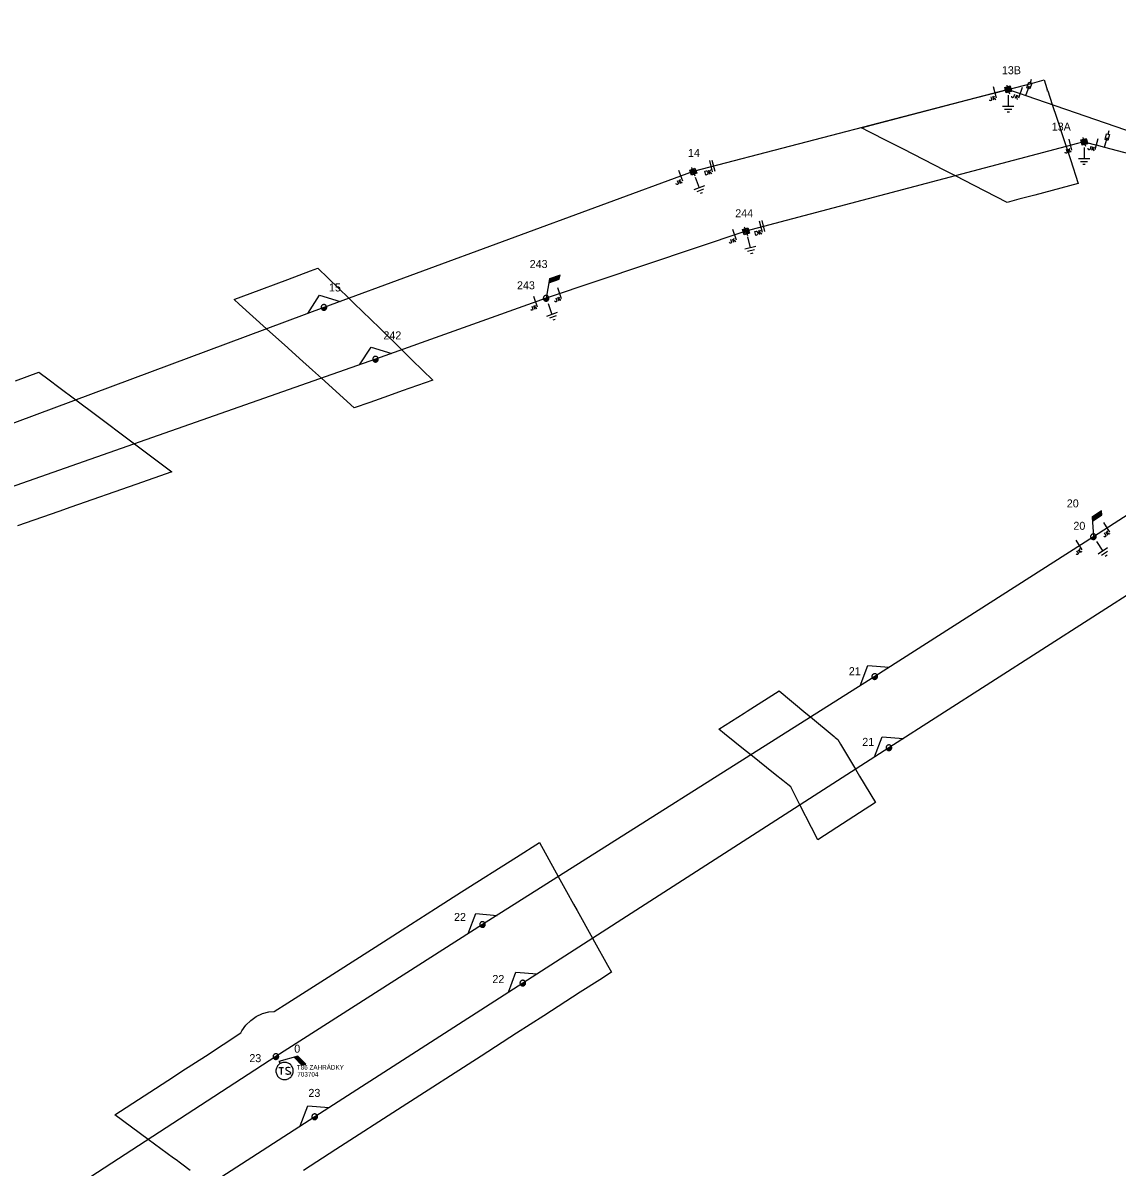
# Model space of a CAD drawing. Extents: x -540879 to -537255, y -1184046 to -1180016.
# Drawn here: x -538995.4 to -538756.2, y -1180861.8 to -1180611.6 of the extents above; entities that cross this region are included whole.
import ezdxf

# ---------------------------------------------------------------- set-up
doc = ezdxf.new("R2010")
doc.units = 0
for name, color, linetype in [('Default', 7, 'Continuous'), ('Vrstva 1', 7, 'Continuous'), ('Vrstva 11', 7, 'Continuous'), ('Vrstva 12', 7, 'Continuous'), ('Vrstva 13', 7, 'Continuous'), ('Vrstva 14', 7, 'Continuous'), ('Vrstva 15', 7, 'Continuous'), ('Vrstva 16', 7, 'Continuous'), ('Vrstva 18', 7, 'Continuous'), ('Vrstva 2', 7, 'Continuous'), ('Vrstva 25', 7, 'Continuous'), ('Vrstva 26', 7, 'Continuous'), ('Vrstva 27', 7, 'Continuous'), ('Vrstva 35', 7, 'Continuous'), ('Vrstva 4', 7, 'Continuous'), ('Vrstva 6', 7, 'Continuous')]:
    doc.layers.add(name, color=color, linetype=linetype)

# ---------------------------------------------------------------- blocks, each defined once
blk = doc.blocks.new('VN850')
at = {"layer": 'Vrstva 15'}
for points in [[(-0.56, 1.43), (-0.56, -1.07)], [(-0.01, 1.43), (-0.01, -1.07)], [(-2.09, -0.54), (-1.78, -0.54)], [(-2.09, -1.41), (-2.09, -0.54)], [(-1.78, -1.41), (-2.09, -1.41)], [(-1.78, -0.54), (-1.66, -0.6)], [(-1.67, -1.35), (-1.78, -1.41)], [(-1.59, -1.2), (-1.67, -1.35)], [(-1.66, -0.6), (-1.59, -0.75)], [(-1.59, -0.75), (-1.55, -0.96)], [(-1.55, -0.96), (-1.59, -1.2)], [(-1.26, -0.54), (-1.26, -1.41)], [(-0.85, -0.54), (-1.26, -1.09)], [(-1.13, -0.92), (-0.77, -1.41)]]:
    blk.add_lwpolyline(points, dxfattribs=at)
blk = doc.blocks.new('VN840')
at = {"layer": 'Vrstva 15'}
for points in [[(-0.01, 1.41), (-0.01, -1.09)], [(-1.51, -1.24), (-1.51, -1.15)], [(-1.48, -1.35), (-1.51, -1.24)], [(-1.33, -1.42), (-1.48, -1.35)], [(-1.27, -1.42), (-1.33, -1.42)], [(-1.13, -1.35), (-1.27, -1.42)], [(-1.09, -1.24), (-1.13, -1.35)], [(-1.09, -0.59), (-1.09, -1.24)], [(-0.68, -0.59), (-0.68, -1.42)], [(-0.68, -1.11), (-0.27, -0.59)], [(-0.54, -0.94), (-0.2, -1.42)]]:
    blk.add_lwpolyline(points, dxfattribs=at)
blk = doc.blocks.new('VN860')
at = {"layer": 'Vrstva 15'}
for points in [[(-3.74, 0), (0.01, 2.82)], [(0.01, 2.82), (3.76, 0)]]:
    blk.add_lwpolyline(points, dxfattribs=at)
blk = doc.blocks.new('VN440')
at = {"layer": 'Vrstva 2'}
for points in [[(1.22, 0), (1.21, 0.13), (1.19, 0.25), (1.16, 0.38), (1.11, 0.5), (1.05, 0.61), (0.98, 0.72), (0.9, 0.82), (0.81, 0.91), (0.71, 0.99), (0.6, 1.06), (0.49, 1.12), (0.37, 1.16), (0.25, 1.2), (0.12, 1.22), (-0.01, 1.22), (-0.14, 1.22), (-0.26, 1.2), (-0.39, 1.16), (-0.51, 1.12), (-0.62, 1.06), (-0.73, 0.99), (-0.83, 0.91), (-0.92, 0.82), (-1, 0.72), (-1.07, 0.61), (-1.13, 0.5), (-1.18, 0.38), (-1.21, 0.25), (-1.23, 0.13), (-1.24, 0), (-1.23, -0.13), (-1.21, -0.26), (-1.18, -0.38), (-1.13, -0.5), (-1.07, -0.62), (-1, -0.73), (-0.92, -0.83), (-0.83, -0.92), (-0.73, -1), (-0.62, -1.07), (-0.51, -1.13), (-0.39, -1.17), (-0.26, -1.2), (-0.14, -1.23), (-0.01, -1.23), (0.12, -1.23), (0.25, -1.2), (0.37, -1.17), (0.49, -1.13), (0.6, -1.07), (0.71, -1), (0.81, -0.92), (0.9, -0.83), (0.98, -0.73), (1.05, -0.62), (1.11, -0.5), (1.16, -0.38), (1.19, -0.26), (1.21, -0.13), (1.22, 0)], [(-1.24, 0), (1.22, 0)], [(-1.18, -0.34), (1.1, -0.34)], [(-1.01, -0.63), (0.97, -0.63)], [(-0.74, -0.92), (0.68, -0.92)]]:
    blk.add_lwpolyline(points, dxfattribs=at)
blk = doc.blocks.new('VN820')
at = {"layer": 'Vrstva 13'}
for points in [[(0, 0), (0, -2.1)], [(-0.32, -1.63), (0.34, -1.63)], [(-0.32, -2.95), (-0.32, -1.63)], [(0, -2.1), (-0.12, -1.86)], [(0, -2.1), (0.12, -1.86)], [(0.34, -1.63), (0.34, -2.95)], [(0.34, -2.95), (-0.32, -2.95)], [(0, -2.95), (0, -3.75)]]:
    blk.add_lwpolyline(points, dxfattribs=at)
blk = doc.blocks.new('VN810')
at = {"layer": 'Vrstva 14'}
for points in [[(0, -1.25), (0, -3.75)], [(1.25, -3.75), (-1.25, -3.75)], [(0.77, -4.37), (-0.8, -4.37)], [(0, -5), (-0.25, -5)], [(0.27, -5), (0, -5)]]:
    blk.add_lwpolyline(points, dxfattribs=at)
blk = doc.blocks.new('VN610')
at = {"layer": 'Vrstva 6'}
for points in [[(1.88, 0), (1.87, 0.2), (1.84, 0.39), (1.79, 0.58), (1.72, 0.77), (1.63, 0.94), (1.52, 1.11), (1.4, 1.26), (1.26, 1.4), (1.1, 1.53), (0.94, 1.63), (0.76, 1.72), (0.58, 1.8), (0.39, 1.85), (0.19, 1.88), (-0.01, 1.89), (-0.21, 1.88), (-0.4, 1.85), (-0.59, 1.8), (-0.78, 1.72), (-0.95, 1.63), (-1.12, 1.53), (-1.27, 1.4), (-1.41, 1.26), (-1.54, 1.11), (-1.64, 0.94), (-1.73, 0.77), (-1.8, 0.58), (-1.86, 0.39), (-1.89, 0.2), (-1.9, 0), (-1.89, -0.2), (-1.86, -0.39), (-1.8, -0.58), (-1.73, -0.77), (-1.64, -0.95), (-1.54, -1.11), (-1.41, -1.27), (-1.27, -1.41), (-1.12, -1.53), (-0.95, -1.64), (-0.78, -1.73), (-0.59, -1.8), (-0.4, -1.85), (-0.21, -1.88), (-0.01, -1.89), (0.19, -1.88), (0.39, -1.85), (0.58, -1.8), (0.76, -1.73), (0.94, -1.64), (1.1, -1.53), (1.26, -1.41), (1.4, -1.27), (1.52, -1.11), (1.63, -0.95), (1.72, -0.77), (1.79, -0.58), (1.84, -0.39), (1.87, -0.2), (1.88, 0)], [(-1.27, 0.78), (-0.26, 0.78)], [(-0.76, 0.78), (-0.76, -0.79)], [(1.19, 0.66), (0.94, 0.78), (0.62, 0.78), (0.37, 0.66), (0.24, 0.47), (0.24, 0.4), (0.37, 0.22), (1.12, -0.16), (1.25, -0.32), (1.25, -0.48), (1.12, -0.67), (0.87, -0.79), (0.62, -0.79), (0.49, -0.73), (0.24, -0.6)]]:
    blk.add_lwpolyline(points, dxfattribs=at)
blk = doc.blocks.new('VN001')
at = {"layer": 'Default'}
for p, q in [((1.73, 3.03), (4.14, 3.03)), ((1.76, 3.08), (4.17, 3.08)), ((1.79, 3.13), (4.2, 3.13)), ((1.82, 3.18), (4.23, 3.18)), ((1.85, 3.23), (4.26, 3.23)), ((1.87, 3.28), (4.29, 3.28)), ((1.9, 3.33), (4.32, 3.33)), ((1.93, 3.38), (4.35, 3.38)), ((1.96, 3.43), (4.37, 3.43)), ((1.99, 3.48), (4.4, 3.48)), ((2.02, 3.53), (4.43, 3.53)), ((2.05, 3.58), (4.46, 3.58)), ((2.07, 3.63), (4.49, 3.63)), ((2.1, 3.68), (4.52, 3.68)), ((2.13, 3.73), (2.54, 3.73))]:
    blk.add_line(p, q, dxfattribs=at)
blk.add_lwpolyline([(2.13, 3.73), (0, 0)], dxfattribs=at)
blk.add_lwpolyline([(4.55, 3.73), (2.13, 3.73), (1.7, 2.98), (4.12, 2.99)], close=True, dxfattribs=at)
blk = doc.blocks.new('VN470')
at = {"layer": 'Vrstva 2'}
for points in [[(-1.23, 1.22), (1.23, 1.22)], [(-1.23, -1.23), (-1.23, 1.22)], [(-0.92, 0.9), (0.92, 0.9)], [(-0.92, -0.95), (-0.92, 0.9)], [(-0.61, 0.61), (0.61, 0.61)], [(-0.61, -0.62), (-0.61, 0.61)], [(-0.31, -0.27), (-0.31, 0.34)], [(-0.31, 0.34), (0.31, 0.34)], [(0, 1.22), (0, 1.97)], [(0.31, 0.34), (0.31, -0.27)], [(0.61, 0.61), (0.61, -0.62)], [(0.92, 0.9), (0.92, -0.95)], [(1.23, 1.22), (1.23, -1.23)], [(1.23, -1.23), (-1.23, -1.23)], [(0.92, -0.95), (-0.92, -0.95)], [(0.61, -0.62), (-0.61, -0.62)], [(0.31, -0.27), (-0.31, -0.27)], [(0, -1.23), (0, -1.98)]]:
    blk.add_lwpolyline(points, dxfattribs=at)

msp = doc.modelspace()

# ---------------------------------------------------------------- linework, layer by layer
at = {"layer": 'Vrstva 1'}
for points in [[(-538763.41, -1180637.58), (-538761.55, -1180638.07), (-538760.78, -1180638.27), (-538758.95, -1180638.76), (-538709.24, -1180651.86), (-538611.41, -1180679.1), (-538608.89, -1180679.8), (-538607.32, -1180677.78), (-538533.8, -1180583.25), (-538532.49, -1180581.57), (-538530.42, -1180580.29), (-538435.45, -1180522.72)], [(-538780.03, -1180626.12), (-538778.54, -1180626.64), (-538777.41, -1180627.03), (-538776.14, -1180627.46), (-538708.94, -1180650.67), (-538611.11, -1180678.01), (-538609.12, -1180678.56), (-538608.05, -1180677.18), (-538534.75, -1180582.52), (-538533.61, -1180581.05), (-538532.85, -1180581.05)], [(-538780.03, -1180626.12), (-538848.86, -1180644.11), (-538929.59, -1180673.79), (-539018.19, -1180706.82), (-539073.96, -1180725.94), (-539104.29, -1180736.57)], [(-538763.41, -1180637.58), (-538764.88, -1180637.95), (-538837.36, -1180657.15), (-538881.02, -1180671.8)], [(-538677.51, -1180669.82), (-538718.36, -1180696.18), (-538761.4, -1180723.93)], [(-538881.02, -1180671.8), (-538918.31, -1180685.12), (-539006.53, -1180716.06), (-539088.82, -1180744.46), (-539156.66, -1180768.11), (-539223.23, -1180791.54), (-539293.94, -1180858.74)], [(-538761.4, -1180723.93), (-538809.21, -1180754.51), (-538894.93, -1180808.73), (-538940.09, -1180837.62)], [(-538750.35, -1180734.36), (-538806.1, -1180770.08), (-538886.12, -1180821.54), (-538931.61, -1180850.77), (-539020.62, -1180908.27), (-539099.07, -1180958.39), (-539182.51, -1181012.88)], [(-538940.09, -1180837.62), (-539028.57, -1180895.14), (-539106.08, -1180944.76), (-539187, -1180996.96)]]:
    msp.add_lwpolyline(points, dxfattribs=at)
at = {"layer": 'Vrstva 35'}
for points in [[(-538771.55, -1180625.94), (-538771.53, -1180626.12), (-538771.56, -1180626.4), (-538771.37, -1180626.46), (-538770.39, -1180629.45), (-538769.41, -1180632.43), (-538767.74, -1180637.5), (-538767.38, -1180638.61), (-538766.45, -1180641.45), (-538764.71, -1180646.7), (-538774.22, -1180649.22), (-538777.7, -1180650.14), (-538780.25, -1180650.82), (-538787.5, -1180647.12), (-538791.58, -1180645.03), (-538793.86, -1180643.86), (-538800.77, -1180640.32), (-538802.9, -1180639.23), (-538806.28, -1180637.5), (-538810.4, -1180635.4), (-538812.13, -1180634.51), (-538811.85, -1180634.44), (-538808.58, -1180633.58), (-538787.5, -1180628.07), (-538780.03, -1180626.12), (-538774.73, -1180624.73), (-538772.16, -1180624.06)], [(-538924.14, -1180671.79), (-538922.95, -1180672.95), (-538919.35, -1180676.46), (-538917.4, -1180678.37), (-538912.58, -1180683.07), (-538912.5, -1180683.15), (-538910.3, -1180685.3), (-538908.04, -1180687.5), (-538905.81, -1180689.68), (-538912.5, -1180692.07), (-538915.48, -1180693.13), (-538919.56, -1180694.56), (-538922.96, -1180695.75), (-538930.15, -1180689.27), (-538932.11, -1180687.5), (-538934.95, -1180684.95), (-538935.01, -1180684.89), (-538937.34, -1180682.78), (-538937.5, -1180682.64), (-538942.13, -1180678.47), (-538948.09, -1180673.09), (-538949.24, -1180672.05), (-538949.05, -1180671.98), (-538945.74, -1180670.74), (-538937.5, -1180667.67), (-538932.54, -1180665.82), (-538930.89, -1180665.22)], [(-538824.25, -1180762.5), (-538823.21, -1180763.36), (-538818.04, -1180767.65), (-538817.83, -1180767.83), (-538817.28, -1180768.28), (-538816.68, -1180769.29), (-538813.4, -1180774.77), (-538812.5, -1180776.27), (-538809.03, -1180782.07), (-538812.5, -1180784.3), (-538817.48, -1180787.5), (-538821.66, -1180790.19), (-538823.03, -1180787.5), (-538825.54, -1180782.58), (-538827.53, -1180778.67), (-538828.16, -1180778.16), (-538829.28, -1180777.26), (-538830.93, -1180775.94), (-538836.29, -1180771.64), (-538837.5, -1180770.67), (-538842.03, -1180767.03), (-538843.3, -1180766.02), (-538837.74, -1180762.5), (-538837.5, -1180762.35), (-538837.09, -1180762.09), (-538830.09, -1180757.66)]]:
    msp.add_lwpolyline(points, close=True, dxfattribs=at)
for points in [[(-538997, -1180689.85), (-538991.87, -1180687.94), (-538989.62, -1180689.62), (-538987.5, -1180691.22), (-538983.79, -1180694), (-538979.19, -1180697.46), (-538975.72, -1180700.06), (-538975.34, -1180700.34), (-538971.01, -1180703.6), (-538962.82, -1180709.74), (-538970.69, -1180712.5), (-538984.93, -1180717.49), (-538987.5, -1180718.39), (-538996.57, -1180721.57)], [(-538958.86, -1180862.5), (-538960.68, -1180861.15), (-538960.95, -1180860.95), (-538961.92, -1180860.23), (-538962.5, -1180859.8), (-538967.97, -1180855.75), (-538975.26, -1180850.35), (-538962.5, -1180842.05), (-538960.63, -1180840.83), (-538955.5, -1180837.5), (-538947.72, -1180832.44), (-538947.5, -1180831.97), (-538946.65, -1180830.76), (-538945.6, -1180829.71), (-538944.39, -1180828.86), (-538943.05, -1180828.23), (-538941.61, -1180827.85), (-538940.43, -1180827.74), (-538937.5, -1180825.87), (-538929.47, -1180820.74), (-538916.59, -1180812.5), (-538912.5, -1180809.88), (-538905.23, -1180805.23), (-538899.49, -1180801.56), (-538887.5, -1180793.98), (-538882.49, -1180790.81), (-538878.37, -1180798.25), (-538876.54, -1180801.54), (-538875.02, -1180804.29), (-538874.24, -1180805.7), (-538870.89, -1180811.74), (-538870.47, -1180812.5), (-538867.63, -1180817.63), (-538866.76, -1180819.19), (-538869.29, -1180820.82), (-538873.57, -1180823.57), (-538881.53, -1180828.69), (-538887.5, -1180832.53), (-538895.23, -1180837.5), (-538912.5, -1180848.6), (-538927, -1180857.92), (-538934.09, -1180862.5)]]:
    msp.add_lwpolyline(points, dxfattribs=at)
at = {"layer": 'Vrstva 4'}
msp.add_lwpolyline([(-538939.43, -1180838.67), (-538939.19, -1180839.06)], dxfattribs=at)

# ---------------------------------------------------------------- block references
at = {"layer": 'Vrstva 11'}
for p, rotation in [((-538881.02, -1180671.8), 19.647413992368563), ((-538761.4, -1180723.93), 33.319152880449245), ((-538939.43, -1180838.67), -45.15549252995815)]:
    msp.add_blockref('VN001', p, dxfattribs=dict(at, rotation=rotation))
at = {"layer": 'Vrstva 13'}
for name, p, xscale, yscale, rotation in [('VN470', (-538780.03, -1180626.12), 0.5, 0.5000000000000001, 14.647314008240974), ('VN470', (-538763.41, -1180637.58), 0.5000000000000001, 0.5, 14.82443327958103), ('VN470', (-538848.86, -1180644.11), 0.49999999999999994, 0.5000000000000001, 20.18851399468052), ('VN470', (-538837.36, -1180657.15), 0.5, 0.49999999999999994, 18.54947787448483), ('VN440', (-538881.02, -1180671.8), 0.49999999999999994, 0.5, 19.64747219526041), ('VN440', (-538929.59, -1180673.79), 0.5, 0.5, 20.44437496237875), ('VN440', (-538918.31, -1180685.12), 0.5, 0.5, 19.327486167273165), ('VN440', (-538761.4, -1180723.93), 0.5, 0.4999999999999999, 32.80688886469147), ('VN440', (-538809.21, -1180754.51), 0.49999999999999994, 0.5000000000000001, 32.69993621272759), ('VN440', (-538806.1, -1180770.08), 0.5, 0.5, 32.651983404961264), ('VN440', (-538894.93, -1180808.73), 0.5, 0.5, 32.04686383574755), ('VN440', (-538886.12, -1180821.54), 0.5, 0.5, 32.742499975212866), ('VN440', (-538940.09, -1180837.62), 0.5, 0.49999999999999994, 33.00175841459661), ('VN440', (-538931.61, -1180850.77), 0.5, 0.5000000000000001, 32.731597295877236)]:
    msp.add_blockref(name, p, dxfattribs=dict(at, xscale=xscale, yscale=yscale, rotation=rotation))
at = {"layer": 'Vrstva 15'}
for p, rotation in [((-538780.03, -1180626.12), 0.17704438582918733), ((-538763.41, -1180637.58), -0.5224527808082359), ((-538848.86, -1180644.11), 20.188905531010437), ((-538837.36, -1180657.15), 14.837452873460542), ((-538881.02, -1180671.8), 19.64841937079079), ((-538761.4, -1180723.93), 33.31915276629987)]:
    msp.add_blockref('VN810', p, dxfattribs=dict(at, rotation=rotation))
at = {"layer": 'Vrstva 16'}
for p, rotation in [((-538776.14, -1180627.46), 160.95755839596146), ((-538758.95, -1180638.76), 165.2124750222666)]:
    msp.add_blockref('VN820', p, dxfattribs=dict(at, rotation=rotation))
at = {"layer": 'Vrstva 18'}
for name, p, rotation in [('VN840', (-538782.93, -1180626.88), 14.647844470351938), ('VN840', (-538777.41, -1180627.02), -19.0495472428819), ('VN840', (-538766.43, -1180638.36), 14.837452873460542), ('VN840', (-538760.78, -1180638.27), -14.773289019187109), ('VN840', (-538851.59, -1180645.12), 20.18867221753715), ('VN850', (-538844.44, -1180642.95), 14.666750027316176), ('VN850', (-538833.53, -1180656.14), 14.837452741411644), ('VN840', (-538839.85, -1180657.99), 18.549447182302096), ('VN860', (-538929.59, -1180673.79), 20.44434725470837), ('VN840', (-538883.32, -1180672.63), 19.647594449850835), ('VN840', (-538878.06, -1180670.81), 18.549447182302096), ('VN860', (-538918.31, -1180685.12), 19.647594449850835), ('VN840', (-538758.45, -1180722.03), 32.80688886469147), ('VN840', (-538764.5, -1180725.91), 32.6037668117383), ('VN860', (-538809.21, -1180754.51), 32.69960279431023), ('VN860', (-538806.1, -1180770.08), 32.651983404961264), ('VN860', (-538894.93, -1180808.73), 32.046627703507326), ('VN860', (-538886.12, -1180821.54), 32.742499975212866), ('VN860', (-538931.61, -1180850.77), 32.7315971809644)]:
    msp.add_blockref(name, p, dxfattribs=dict(at, rotation=rotation))
at = {"layer": 'Vrstva 25'}
msp.add_blockref('VN610', (-538938.18, -1180840.77), dxfattribs=at)

# ---------------------------------------------------------------- texts
at = {"layer": 'Vrstva 12'}
for s, p in [('243', (-538884.62, -1180665.19)), ('20', (-538767.22, -1180717.53)), ('0', (-538936.07, -1180836.77))]:
    msp.add_text(s, height=1.75, dxfattribs=at).set_placement(p)
at = {"layer": 'Vrstva 14'}
for s, p in [('13B', (-538781.41, -1180622.8)), ('13A', (-538770.51, -1180635.14)), ('14', (-538850.02, -1180640.89)), ('244', (-538839.69, -1180654.09)), ('15', (-538928.49, -1180670.31)), ('243', (-538887.39, -1180669.84)), ('242', (-538916.59, -1180680.79)), ('20', (-538765.78, -1180722.43)), ('21', (-538814.86, -1180754.22)), ('21', (-538811.93, -1180769.68)), ('22', (-538901.15, -1180807.96)), ('22', (-538892.77, -1180821.54)), ('23', (-538945.89, -1180838.84)), ('23', (-538932.98, -1180846.44))]:
    msp.add_text(s, height=1.75, dxfattribs=at).set_placement(p)
at = {"layer": 'Vrstva 26'}
msp.add_text('703704', height=1, dxfattribs=at).set_placement((-538935.41, -1180841.99))
at = {"layer": 'Vrstva 27'}
msp.add_text('T86 ZAHRÁDKY', height=1, dxfattribs=at).set_placement((-538935.51, -1180840.46))

doc.saveas('drawing.dxf')
